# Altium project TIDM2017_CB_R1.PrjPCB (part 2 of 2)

## Sheet Power_Supply.SchDoc
size 431 x 279 mm; Date: Not shown in title block; ApprovedBy: Not shown in title block; CheckedBy: Not shown in title block; Author: Not shown in title block; CompanyName: Not shown in title block; Engineer: Not shown in title block; Organization: Not shown in title block; Address1: Not shown in title block; Address2: Not shown in title block; Address3: Not shown in title block; Address4: Not shown in title block; DocumentNumber: 2; Revision: Use project parameter SCH_Rev; SheetNumber: 2; SheetTotal: 3; PageSetup: Record=PageOptions¦CenterHorizontal=True¦CenterVertical=True¦PrintScale=1.00¦XCorrection=1.00¦YCorrection=1.00¦PrintKind=0¦BorderSize=5000000¦LeftOffset=0¦BottomOffset=0¦Orientation=2¦PaperLength=1000¦PaperWidth=1000¦Scale=100¦PaperSource=15¦PrintQuality=600¦MediaType=1¦DitherType=10¦PaperKind=Letter¦PrintScaleMode=1
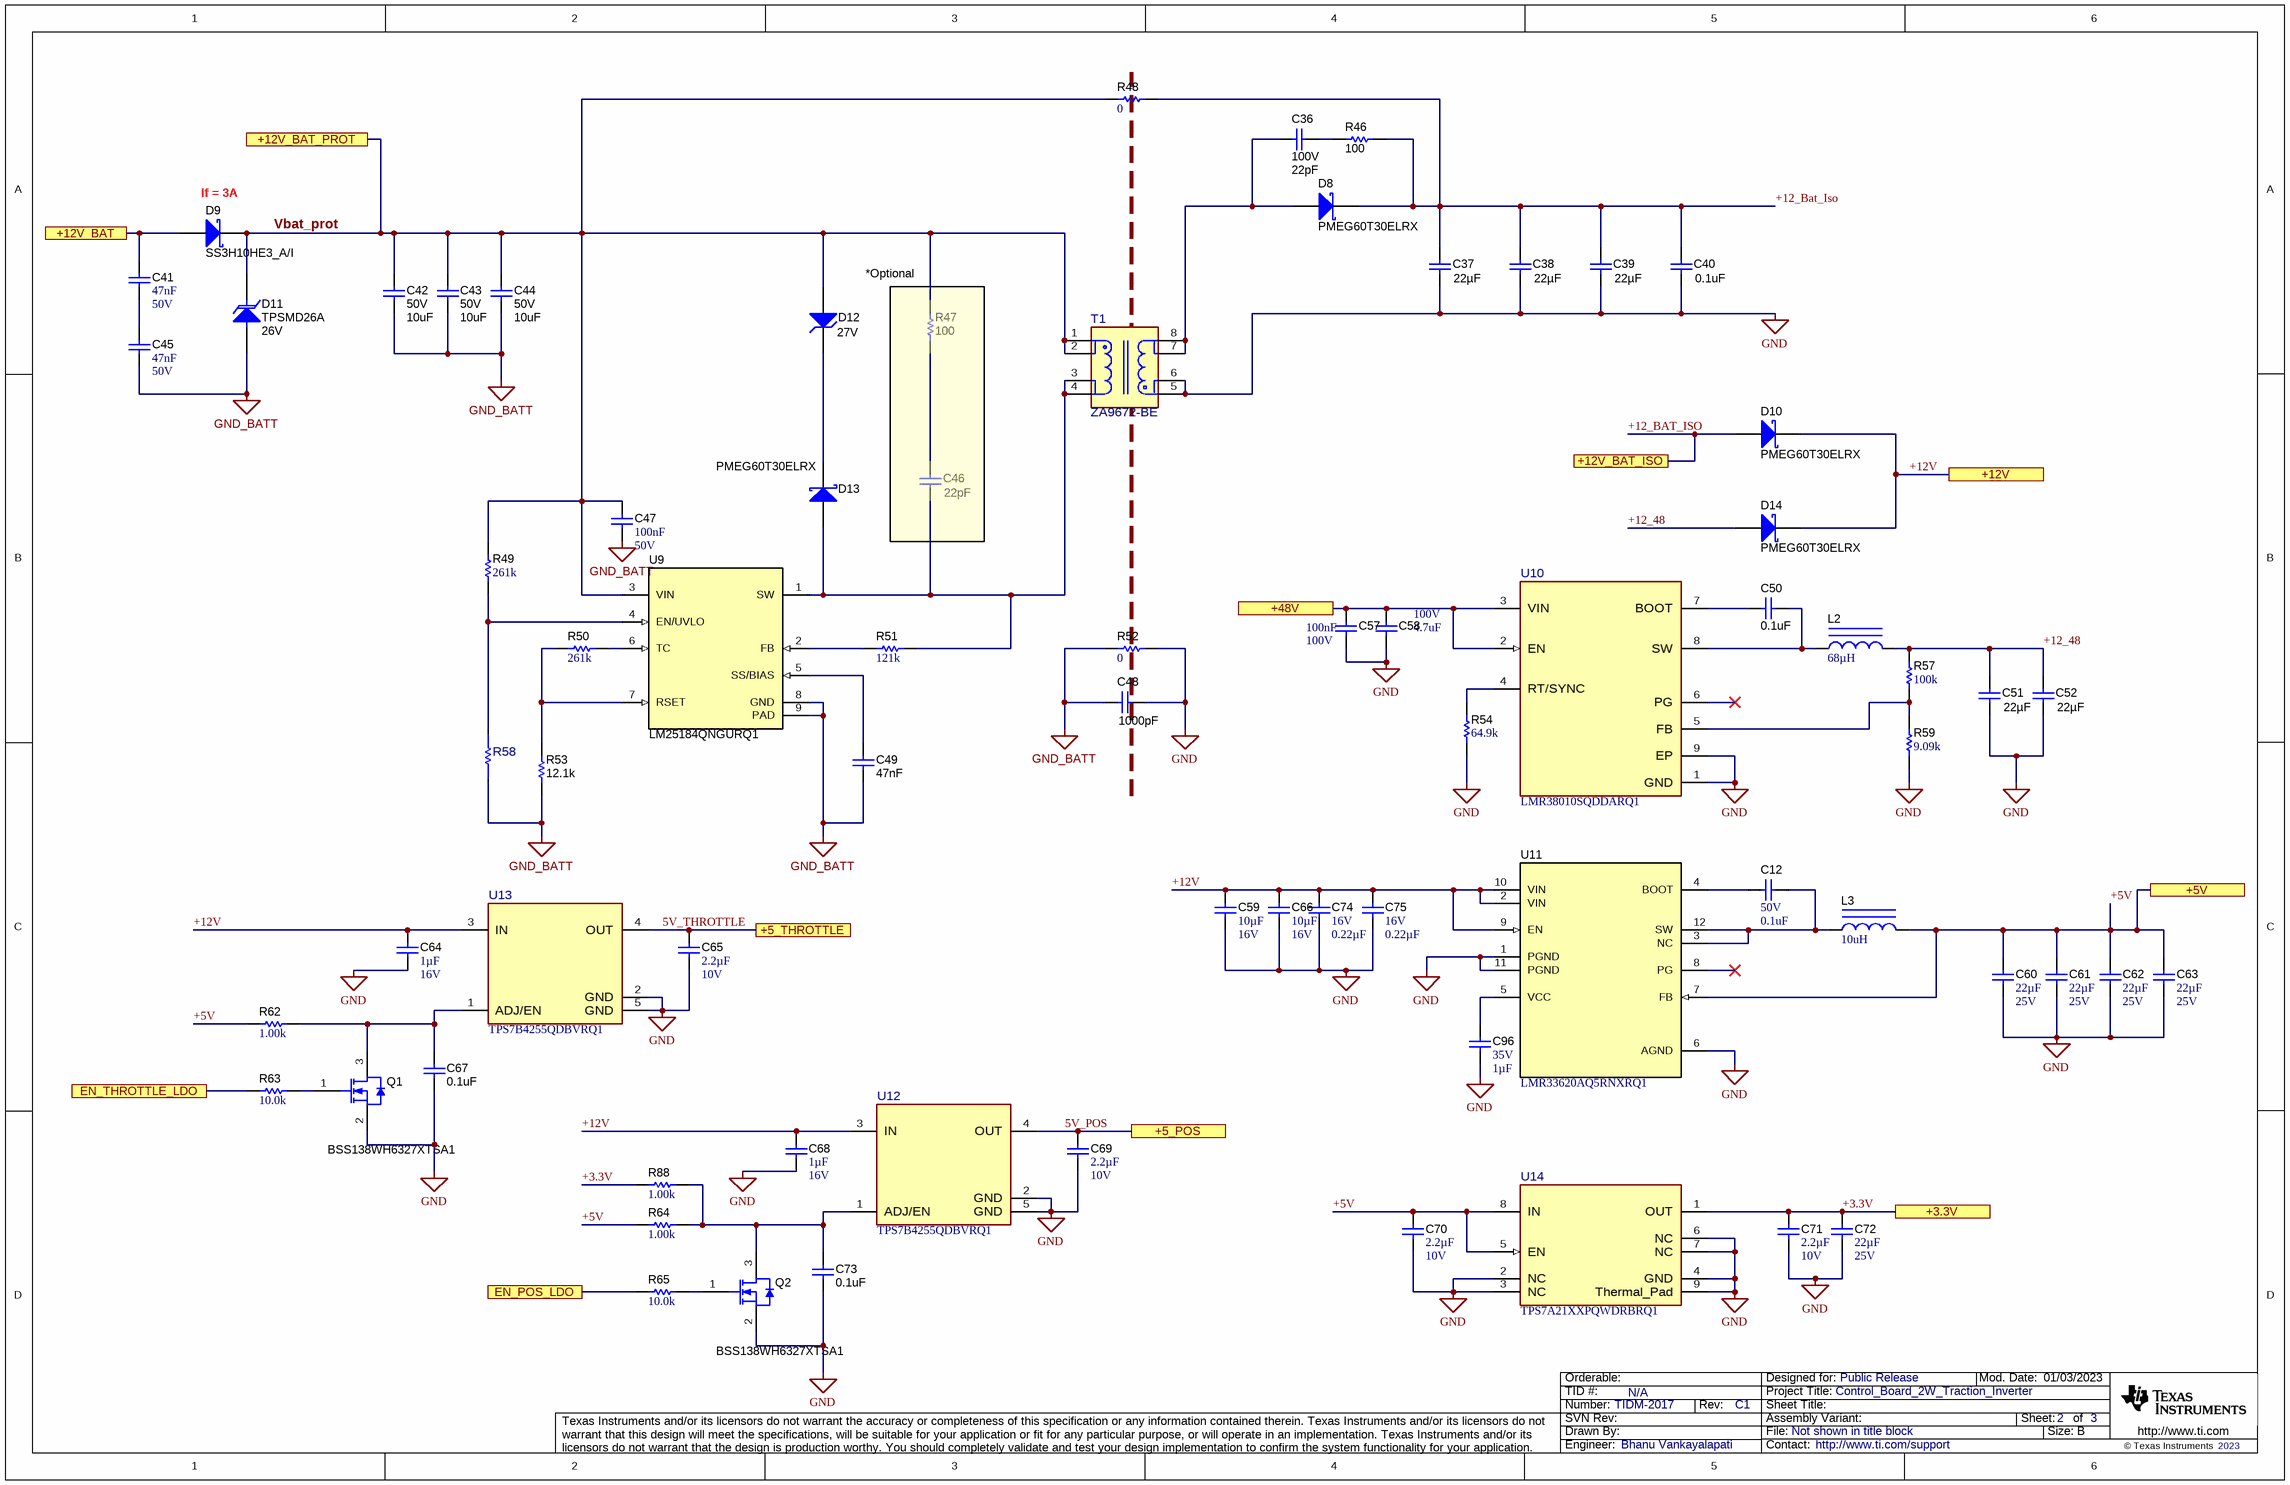
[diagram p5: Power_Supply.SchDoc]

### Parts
C12  VDC_V: 50V  ValueDisplayed: 0.1uF  [0402]  (hidden comment: CGA2B3X7R1H104M050BB)
C36  VDC_V: 100V  ValueDisplayed: 22pF  [0603]  (hidden comment: GRM1885C2A220JA01D)
C37  ValueDisplayed: 22µF  [1210_270]  (hidden comment: TMK325B7226KMHP)
C38  ValueDisplayed: 22µF  [1210_270]  (hidden comment: TMK325B7226KMHP)
C39  ValueDisplayed: 22µF  [1210_270]  (hidden comment: TMK325B7226KMHP)
C40  value 0.1uF  [0603]  (hidden comment: C0603C104K5RACAUTO)
C41  Cap_F: 47nF  VDC_V: 50V  [0603]  (hidden comment: CGA3E2X7R1H473K080AA)
C42  VDC_V: 50V  ValueDisplayed: 10uF  [1210_280]  (hidden comment: CGA6P3X7S1H106K250AB)
C43  VDC_V: 50V  ValueDisplayed: 10uF  [1210_280]  (hidden comment: CGA6P3X7S1H106K250AB)
C44  VDC_V: 50V  ValueDisplayed: 10uF  [1210_280]  (hidden comment: CGA6P3X7S1H106K250AB)
C45  Cap_F: 47nF  VDC_V: 50V  [0603]  (hidden comment: CGA3E2X7R1H473K080AA)
C46  ValueDisplayed: 22pF  [0603_HV]  (hidden comment: GRM1885C2A220JA01D)
C47  Cap_F: 100nF  VDC_V: 50V  [0603]  (hidden comment: C0603C104K5RACTU)
C48  ValueDisplayed: 1000pF  [1206_190M]  (hidden comment: 202R18W102KV4E)
C49  Cap_F: 47nF  [0603]  (hidden comment: GCM188R71E473KA37D)
C50  value 0.1uF  [0603]  (hidden comment: C0603C104K5RACAUTO)
C51  ValueDisplayed: 22µF  [1210_270]  (hidden comment: TMK325B7226KMHP)
C52  ValueDisplayed: 22µF  [1210_270]  (hidden comment: TMK325B7226KMHP)
C57  Cap_F: 100nF  VDC_V: 100V  [0805_HV]  (hidden comment: GCM21BR72A104KA37L)
C58  VDC_V: 100V  ValueDisplayed: 4.7uF  [2220_250]  (hidden comment: CGA9N2X7R2A475M230KA)
C59  ValueDisplayed: 10µF  VDC_V: 16V  [0603]  (hidden comment: GRT188C81C106ME13D)
C60  ValueDisplayed: 22µF  VDC_V: 25V  [0805_HV]  (hidden comment: GRT21BR61E226ME13L)
C61  ValueDisplayed: 22µF  VDC_V: 25V  [0805_HV]  (hidden comment: GRT21BR61E226ME13L)
C62  ValueDisplayed: 22µF  VDC_V: 25V  [0805_HV]  (hidden comment: GRT21BR61E226ME13L)
C63  ValueDisplayed: 22µF  VDC_V: 25V  [0805_HV]  (hidden comment: GRT21BR61E226ME13L)
C64  Cap_F: 1µF  VDC_V: 16V  [0603]  (hidden comment: GCM188R71C105KA64J)
C65  Cap_F: 2.2µF  VDC_V: 10V  [0603]  (hidden comment: GRM188R71A225KE15J)
C66  ValueDisplayed: 10µF  VDC_V: 16V  [0603]  (hidden comment: GRT188C81C106ME13D)
C67  value 0.1uF  [0603]  (hidden comment: C0603C104K5RACAUTO)
C68  Cap_F: 1µF  VDC_V: 16V  [0603]  (hidden comment: GCM188R71C105KA64J)
C69  Cap_F: 2.2µF  VDC_V: 10V  [0603]  (hidden comment: GRM188R71A225KE15J)
C70  Cap_F: 2.2µF  VDC_V: 10V  [0603]  (hidden comment: GRM188R71A225KE15J)
C71  Cap_F: 2.2µF  VDC_V: 10V  [0603]  (hidden comment: GRM188R71A225KE15J)
C72  ValueDisplayed: 22µF  VDC_V: 25V  [0805_HV]  (hidden comment: GRT21BR61E226ME13L)
C73  value 0.1uF  [0603]  (hidden comment: C0603C104K5RACAUTO)
C74  VDC_V: 16V  ValueDisplayed: 0.22µF  [0402]  (hidden comment: GCM155R71C224KE02D)
C75  VDC_V: 16V  ValueDisplayed: 0.22µF  [0402]  (hidden comment: GCM155R71C224KE02D)
C96  VDC_V: 35V  ValueDisplayed: 1µF  [0402]  (hidden comment: GRT155R6YA105KE13D)
D8  PMEG60T30ELRX  [SOD-123W]
D9  SS3H10HE3_A/I  [SMC_265]
D10  PMEG60T30ELRX  [SOD-123W]
D11  TPSMD26A  value 26V  [SMC_265]
D12  value 27V  [SMA]  (hidden comment: 3SMAJ5935B-TP)
D13  PMEG60T30ELRX  [SOD-123W]
D14  PMEG60T30ELRX  [SOD-123W]
L2  ValueDisplayed: 68µH  [PA4342_2]  (hidden comment: PA4342.683NLT)
L3  ValueDisplayed: 10uH  [SRN6045TA]  (hidden comment: SRN6045TA-100M)
Q1  BSS138WH6327XTSA1  [SOT-323]
Q2  BSS138WH6327XTSA1  [SOT-323]
R46  ValueDisplayed: 100  [0603]  (hidden comment: CRCW0603100RFKEAHP)
R47  ValueDisplayed: 100  [0603]  (hidden comment: CRCW0603100RFKEA)
R48  ValueDisplayed: 0  [1206]  (hidden comment: RCA12060000ZSEA)
R49  ValueDisplayed: 261k  [0603]  (hidden comment: CRCW0603261KFKEA)
R50  ValueDisplayed: 261k  [0603]  (hidden comment: CRCW0603261KFKEA)
R51  ValueDisplayed: 121k  [0603]  (hidden comment: CRCW0603121KFKEA)
R52  ValueDisplayed: 0  [1206]  (hidden comment: RCA12060000ZSEA)
R53  ValueDisplayed: 12.1k  [0603]  (hidden comment: CRCW060312K1FKEA)
R54  ValueDisplayed: 64.9k  [0603]  (hidden comment: CRCW060364K9FKEA)
R57  ValueDisplayed: 100k  [0603]  (hidden comment: ERA-3ARW104V)
R58  ERJ-PB3D9762V  [FP-ERJ-PB3D9762V_0603-MFG]  (value not drawn)
R59  ValueDisplayed: 9.09k  [0603]  (hidden comment: CRCW06039K09FKEA)
R62  ValueDisplayed: 1.00k  [0603]  (hidden comment: CRCW06031K00FKEA)
R63  ValueDisplayed: 10.0k  [0603]  (hidden comment: RMCF0603FT10K0)
R64  ValueDisplayed: 1.00k  [0603]  (hidden comment: CRCW06031K00FKEA)
R65  ValueDisplayed: 10.0k  [0603]  (hidden comment: RMCF0603FT10K0)
R88  ValueDisplayed: 1.00k  [0603]  (hidden comment: CRCW06031K00FKEA)
T1  ZA9672-BE  [FP-ZA9672-BE_SMD8-MFG]
U9  LM25184QNGURQ1  [NGU0008C]
U10  LMR38010SQDDARQ1  [DDA0008E-MFG]
U11  LMR33620AQ5RNXRQ1  [RNX0012B]
U12  TPS7B4255QDBVRQ1  [DBV0005A-MFG]
U13  TPS7B4255QDBVRQ1  [DBV0005A-MFG]
U14  TPS7A21XXPQWDRBRQ1  [DRB0008K-MFG]

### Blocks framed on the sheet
*Optional: C46 R47

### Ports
+3.3V, +5_POS, +5_THROTTLE, +5V, +12V, +12V_BAT, +12V_BAT_ISO, +12V_BAT_PROT, +48V, EN_POS_LDO, EN_THROTTLE_LDO

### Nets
+3.3V: C71.1 C72.1 R88.1 U14.1(OUT) ; port +3.3V
+5V: C60.1 C61.1 C62.1 C63.1 C70.1 L3.2 R62.1 R64.1 U11.7(FB) U14.5(EN) U14.8(IN) ; port +5V
GND: C37.2 C38.2 C39.2 C40.2 C48.1 C51.2 C52.2 C57.2 C58.2 C59.2 C60.2 C61.2 C62.2 C63.2 C64.2 C65.2 C66.2 C67.1 C68.2 C69.2 C70.2 C71.2 C72.2 C73.1 C74.2 C75.2 C96.2 Q1.2(S) Q2.2(S) R52.2 R54.1 R59.1 T1.5 T1.6 U10.1(GND) U10.9(EP) U11.1(PGND) U11.6(AGND) U11.11(PGND) U12.2(GND) U12.5(GND) U13.2(GND) U13.5(GND) U14.2(NC) U14.3(NC) U14.4(GND) U14.6(NC) U14.7(NC) U14.9(Thermal_Pad)
GND_BATT: C42.1 C43.1 C44.1 C45.2 C47.2 C48.2 C49.2 D11.2(A) R52.1 R53.1 R58.1 U9.8(GND) U9.9(PAD)
5V_POS: C69.1 U12.4(OUT) ; port +5_POS  [project net +5_POS]
5V_THROTTLE: C65.1 U13.4(OUT) ; port +5_THROTTLE  [project net +5_THROTTLE]
+12_48: C51.1 C52.1 D14.2(A) L2.2 R57.2
+12_Bat_Iso: C37.1 C38.1 C39.1 C40.1 D8.1(K) D10.2(A) R46.2 R48.2 ; port +12V_BAT_ISO
+12V: C59.1 C64.1 C66.1 C68.1 C74.1 C75.1 D10.1(K) D14.1(K) U11.2(VIN) U11.9(EN) U11.10(VIN) U12.3(IN) U13.3(IN) ; port +12V
+12V_BAT: C41.1 D9.2(A) ; port +12V_BAT
+48V: C57.1 C58.1 U10.2(EN) U10.3(VIN) ; port +48V
EN_POS_LDO: R65.1 ; port EN_POS_LDO
EN_THROTTLE_LDO: R63.1 ; port EN_THROTTLE_LDO
Vbat_prot: C42.2 C43.2 C44.2 C47.1 D9.1(K) D11.1(K) D12.2(A) R47.2 R48.1 R49.2 T1.1 T1.2 U9.3(VIN) ; port +12V_BAT_PROT  [project net +12V_BAT_PROT]
NetC12_1: C12.1 L3.1 U11.3(NC) U11.12(SW)
NetC12_2: C12.2 U11.4(BOOT)
NetC36_1: C36.1 R46.1
NetC36_2: C36.2 D8.2(A) T1.7 T1.8
NetC41_2: C41.2 C45.1
NetC46_1: C46.1 R47.1
NetC46_2: C46.2 D13.2(A) R51.2 T1.3 T1.4 U9.1(SW)
NetC49_1: C49.1 U9.5(SS/BIAS)
NetC50_1: C50.1 U10.7(BOOT)
NetC50_2: C50.2 L2.1 U10.8(SW)
NetC67_2: C67.2 Q1.3(D) R62.2 U13.1(ADJ/EN)
NetC73_2: C73.2 Q2.3(D) R64.2 R88.2 U12.1(ADJ/EN)
NetC96_1: C96.1 U11.5(VCC)
NetD12_1: D12.1(K) D13.1(K)
NetQ1_1: Q1.1(G) R63.2
NetQ2_1: Q2.1(G) R65.2
NetR49_1: R49.1 R58.2 U9.4(EN/UVLO)
NetR50_1: R50.1 R53.2 U9.7(RSET)
NetR50_2: R50.2 U9.6(TC)
NetR51_1: R51.1 U9.2(FB)
NetR54_2: R54.2 U10.4(RT/SYNC)
NetR57_1: R57.1 R59.2 U10.5(FB)

Not connected (* = marked no-connect by the designer): U10 6(PG)*; U11 8(PG)*

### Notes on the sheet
- (near D9) If = 3A

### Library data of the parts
C12 = CMP-0006326-2: CAP, CERM, 0.1 uF, 50 V, +/- 20%, X7R, AEC-Q200 Grade 1, 0402; Manufacturer: TDK; TaMin_C: -55°C; Polarized: N; SizeAreaWB_mm2: 3; Value1: Unknown; U/M: EA; Value: 0.1uF; TaMax_C: 125°C; SizeZ_mm: 0.6; SizeX_mm: 1; SizeY_mm: 0.5; AEC Qualified: Y; Cap_F: 100nF; AEC Category: Q200
C36 = CMP-0007255-4: CAP, CERM, 22 pF, 100 V, +/- 5%, C0G/NP0, 0603; Manufacturer: MuRata; TaMin_C: -55°C; Polarized: N; SizeAreaWB_mm2: 4.68; Value1: Unknown; U/M: EA; Value: 22pF; TaMax_C: 125°C; SizeZ_mm: 1; SizeX_mm: 1.6; SizeY_mm: 0.8; SizeArea_mm2: 1.28; AEC Category: Q200
C37-C39 C51 C52 = CMP-0080552-1: CAP, CERM, 22 µF, 25 V,+/- 10%, X7R, AEC-Q200 Grade 1, 1210; Manufacturer: Taiyo Yuden; TaMin_C: -55°C; Polarized: N; SizeAreaWB_mm2: 14.7; U/M: EA; Value: 22uF; TaMax_C: 125°C; SizeZ_mm: 2.7; SizeX_mm: 3.2; SizeY_mm: 2.5; Cap_Case: 1210; Value2: 25V; SizeArea_mm2: 8; CompType: Capacitor; AEC Qualified: Y; AEC Category: Q200; AEC Grade: 1
C40 C50 C67 C73 = CMP-0079602-1: CAP, CERM, 0.1 µF, 50 V,+/- 10%, X7R, AEC-Q200 Grade 1, 0603; Manufacturer: Kemet; TaMin_C: -55°C; Polarized: N; SizeAreaWB_mm2: 4.68; U/M: EA; TaMax_C: 125°C; SizeZ_mm: 1; SizeX_mm: 1.6; SizeY_mm: 0.8; Value2: 50V; SizeArea_mm2: 1.28; AEC Qualified: Y; Cap_F: 100nF; AEC Category: Q200; ValueDisplayed: 0.1µF
C41 C45 = CMP-0007079-4: CAP, CERM, 0.047 uF, 50 V, +/- 10%, X7R, AEC-Q200 Grade 1, 0603; Manufacturer: TDK; TaMin_C: -55°C; ESR_ohm: 49.007m; Polarized: N; SizeAreaWB_mm2: 4.68; Value1: 0.049007 ohm; U/M: EA; TaMax_C: 125°C; SizeZ_mm: 1; SizeX_mm: 1.6; SizeY_mm: 0.8; SizeArea_mm2: 1.28; AEC Qualified: Y; IRMS_A: 767.528mA; AEC Category: Q200
C42-C44 = CMP-0009164-2: CAP, CERM, 10 uF, 50 V, +/- 10%, X7S, AEC-Q200 Grade 1, 1210; Manufacturer: TDK; TaMin_C: -55°C; Polarized: N; SizeAreaWB_mm2: 14.7; Value1: 0.002827 ohm; U/M: EA; Value: 10uF; TaMax_C: 125°C; SizeZ_mm: 2.8; SizeX_mm: 3.2; SizeY_mm: 2.5; SizeArea_mm2: 8; CompType: Capacitor; AEC Qualified: Y; Cap_F: 10µF; AEC Grade: 1; AEC Category: Q200; ESR_ohm: 2.827m; IRMS_A: 4.37286A
C46 = CMP-0007255-4: CAP, CERM, 22 pF, 100 V, +/- 5%, C0G/NP0, 0603; Manufacturer: MuRata; TaMin_C: -55°C; Polarized: N; SizeAreaWB_mm2: 4.68; Value1: Unknown; U/M: EA; Value: 22pF; TaMax_C: 125°C; SizeZ_mm: 1; SizeX_mm: 1.6; SizeY_mm: 0.8; Cap_Case: 0603; Value2: 100V; SizeArea_mm2: 1.28; CompType: Capacitor; AEC Category: Q200
C47 = CMP-0006861-4: CAP, CERM, 0.1 uF, 50 V, +/- 10%, X7R, 0603; Manufacturer: Kemet; TaMin_C: -55°C; Polarized: N; SizeAreaWB_mm2: 4.68; Value1: Unknown; U/M: EA; Value: 0.1uF; TaMax_C: 125°C; SizeZ_mm: 1; SizeX_mm: 1.6; SizeY_mm: 0.8; SizeArea_mm2: 1.28; AEC Category: Q200
C48 = CMP-0008572-2: CAP, CERM, 1000 pF, 2000 V, +/- 10%, X7R, 1206_190; Manufacturer: Johanson Technology; TaMin_C: -55°C; Polarized: N; SizeAreaWB_mm2: 10.92; Value1: Unknown; U/M: EA; Value: 1000pF; TaMax_C: 125°C; SizeZ_mm: 1.9; SizeX_mm: 3.2; SizeY_mm: 1.6; Cap_Case: 1206; Value2: 2000V; SizeArea_mm2: 5.12; CompType: Capacitor; Cap_F: 1nF; VDC_V: 2kV; AEC Category: Q200
C49 = CMP-0007141-3: CAP, CERM, 0.047 uF, 25 V, +/- 10%, X7R, AEC-Q200 Grade 1, 0603; Manufacturer: MuRata; TaMin_C: -55°C; Polarized: N; SizeAreaWB_mm2: 4.68; Value1: Unknown; U/M: EA; TaMax_C: 125°C; SizeZ_mm: 1; SizeX_mm: 1.6; SizeY_mm: 0.8; Value2: 25V; SizeArea_mm2: 1.28; AEC Qualified: Y; AEC Category: Q200
C57 = CMP-0860440-1: CAP, CERM, 0.1 µF, 100 V,+/- 10%, X7R, AEC-Q200 Grade 1, 0805; Manufacturer: MuRata; SizeY_mm: 1.25; ValueDisplayed: 0.1µF; SizeX_mm: 2; Cap_Case: 0805; AEC Grade: 1; Polarized: N; Value: 0.1uF; TaMin_C: -55°C; SizeZ_mm: 1.45; TaMax_C: 125°C; U/M: EA; SizeArea_mm2: 2.5; AEC Qualified: Y; SizeAreaWB_mm2: 6.75; AEC Category: Q200
C58 = CMP-0009414-2: CAP, CERM, 4.7 uF, 100 V, +/- 20%, X7R, AEC-Q200 Grade 1,; Manufacturer: TDK; TaMin_C: -55°C; Polarized: N; SizeAreaWB_mm2: 53.9; Value1: Unknown; U/M: EA; Value: 4.7uF; TaMax_C: 125°C; SizeZ_mm: 2.5; SizeX_mm: 5.7; SizeY_mm: 5; Cap_Case: 2220; SizeArea_mm2: 28.5; AEC Qualified: Y; Cap_F: 4.7µF; AEC Grade: 1; AEC Category: Q200
C59 C66 = CMP-0085644-1: CAP, CERM, 10 µF, 16 V,+/- 20%, X6S, AEC-Q200 Grade 2, 0603; Manufacturer: MuRata; TaMin_C: -55°C; SizeY_mm: 0.8; SizeX_mm: 1.6; SizeZ_mm: 1; SizeArea_mm2: 1.28; Value: 10uF; AEC Grade: 2; Polarized: N; U/M: EA; TaMax_C: 105°C; AEC Qualified: Y; AEC Category: Q200; SizeAreaWB_mm2: 4.68
C60-C63 C72 = CMP-0084680-1: CAP, CERM, 22 µF, 25 V,+/- 20%, X5R, AEC-Q200 Grade 3, 0805; Manufacturer: MuRata; SizeX_mm: 2; SizeAreaWB_mm2: 6.75; Cap_Case: 0805; AEC Grade: 3; SizeY_mm: 1.25; SizeArea_mm2: 2.5; SizeZ_mm: 1.45; U/M: EA; Polarized: N; AEC Category: Q200; Value: 22uF; TaMin_C: -55°C; AEC Qualified: Y; TaMax_C: 85°C
C64 C68 = CMP-0079154-1: CAP, CERM, 1 µF, 16 V,+/- 10%, X7R, AEC-Q200 Grade 1, 0603; Manufacturer: MuRata; SizeAreaWB_mm2: 4.68; SizeArea_mm2: 1.28; AEC Qualified: Y; AEC Category: Q200; Value: 1uF; TaMax_C: 125°C; SizeZ_mm: 1; Polarized: N; TaMin_C: -55°C; SizeY_mm: 0.8; U/M: EA; SizeX_mm: 1.6
C65 C69-C71 = CMP-0084284-1: CAP, CERM, 2.2 µF, 10 V,+/- 10%, X7R, AEC-Q200 Grade 1, 0603; Manufacturer: MuRata; SizeAreaWB_mm2: 4.68; Polarized: N; AEC Qualified: Y; SizeX_mm: 1.6; SizeZ_mm: 1; SizeY_mm: 0.8; U/M: EA; TaMin_C: -55°C; Value: 2.2uF; AEC Category: Q200; TaMax_C: 125°C; SizeArea_mm2: 1.28
C74 C75 = CMP-0078265-1: CAP, CERM, 0.22 µF, 16 V,+/- 10%, X7R, AEC-Q200 Grade 1, 0402; Manufacturer: MuRata; TaMin_C: -55°C; Polarized: N; SizeAreaWB_mm2: 3; U/M: EA; Value: 0.22uF; TaMax_C: 125°C; SizeZ_mm: 0.6; SizeX_mm: 1; SizeY_mm: 0.5; AEC Qualified: Y; Cap_F: 220nF; AEC Category: Q200
C96 = CMP-0750099-1: CAP, CERM, 1 µF, 35 V,+/- 10%, X5R, AEC-Q200 Grade 3, 0402; Manufacturer: MuRata; AEC Grade: 3; AEC Category: Q200; Value: 1uF; SizeArea_mm2: 0.5; SizeZ_mm: 0.6; AEC Qualified: Y; TaMin_C: -55°C; SizeX_mm: 1; U/M: EA; Polarized: N; TaMax_C: 85°C
D8 D10 D13 D14 = CMP-0085903-1: Diode, Schottky, 60 V, 3 A, AEC-Q101, SOD-123W; Manufacturer: Nexperia; Vr_V: 60V; Value1: 3A; TJmax_C: 175°C; Value: 60V; SizeY_mm: 1.7; SizeZ_mm: 1; Vf_V: 620mV; SizeArea_mm2: 5.95; SizeX_mm: 3.5; Value2: 0.62V; SizeAreaWB_mm2: 12.15; AEC Category: Q101; AEC Qualified: Y
D9 = CMP-0077075-2: Diode, Schottky, 100 V, 3 A, AEC-Q101, SMC; Manufacturer: Vishay-Siliconix; Value1: 3A; SizeY_mm: 5.905; Value2: 0.8V; TJmax_C: 175°C; SizeX_mm: 7.94; SizeZ_mm: 2.62; AEC Qualified: Y; Vf_V: 800mV; AEC Category: Q101; Green_REACh: Incomplete; Green_Lifecycle: Not Set; SizeArea_mm2: 46.8857; Vr_V: 100V; SizeAreaWB_mm2: 78.5757; Value: 100V
D11 = CMP-0005729-4: Diode, TVS, Uni, 26 V, 42.1 Vc, AEC-Q101, SMC; Manufacturer: Littelfuse; Vc: 42.1V; Value1: 3000W; Ipp: 71.3A; SizeAreaWB_mm2: 78.5757; AEC Category: Q101; AEC Qualified: Y; SizeArea_mm2: 46.8857; SizeZ_mm: 2.62; Vbr_Max: 31.9V; RJA_CperW: 75; Vbr_Min: 28.9V; Ppk: 3kW; SizeY_mm: 5.905; SizeX_mm: 7.94
D12 = CMP-0005514-4: Diode, Zener, 27 V, 3 W, SMA; Manufacturer: Micro Commercial Components; SizeX_mm: 5.59; SizeY_mm: 2.92; RJA_CperW: 226; SizeZ_mm: 2.87; Value1: 3W; SizeArea_mm2: 16.3228; SizeAreaWB_mm2: 37.3428; AEC Category: Q101
L2 = CMP-0079799-1: Inductor, Shielded, 68 µH, 2 A, 0.24 ohm, AEC-Q200 Grade 1, SMD; Manufacturer: Pulse Engineering; SizeAreaWB_mm2: 166.05; Irms: 2A @ 40C rise; SizeArea_mm2: 118.45; AEC Qualified: Y; AEC Category: Q200; Value: 68uH; SizeZ_mm: 4; Imax_A: 2A; AEC Grade: 1; SizeY_mm: 10.3; Isat: 3A @ 30% inductance drop; DCR_ohm: 0.24; SizeX_mm: 11.5
L3 = CMP-0056765-1: Inductor, Shielded, Ferrite, 10 uH, 3.2 A, 0.0624 ohm, AEC-Q200 Grade 1, SMD; Manufacturer: Bourns; Isat: 4.6A @ 30% inductance drop; Irms: 3.2A @ 40C rise; Green_Lifecycle: Active; SizeAreaWB_mm2: 64; DCR_ohm: 62.4m; Green_REACh: Passed; Value: 10uH; Imax_A: 3.2A; SizeZ_mm: 4.5; SizeX_mm: 6; SizeArea_mm2: 36; Ind_H: 10µH; AEC Qualified: Y; AEC Grade: 1; AEC Category: Q200
Q1 Q2 = CMP-0000791-1: MOSFET, N-CH, 60 V, 0.28 A, AEC-Q101, SOT-323; Alternate Manufacturer: None; Manufacturer: Infineon Technologies; SizeZ_mm: 1.1; ChType: N; Value2: 1 nC; VdsMax_V: 60V; SizeX_mm: 2.2; Vgs_V: 20V; QgTyp_nC: 1; AEC Qualified: Y; Value: 60V; Rdson45_ohm: 4; SizeArea_mm2: 4.84; AEC Category: Q101; IdsMax_A: 280mA; SizeAreaWB_mm2: 10.24; U/M: EA
R46 = CMP-0084243-1: RES, 100, 1%, 0.25 W, AEC-Q200 Grade 0, 0603; Manufacturer: Vishay-Dale; Power_W: 250mW; TempCo: 100 ppm/C; SizeAreaWB_mm2: 4.68; Value_Code: 100R; Value: 100; EIA_Code: E96; SizeX_mm: 1.6; SizeY_mm: 0.8; SizeZ_mm: 1; Value2: 0.25W; SizeArea_mm2: 1.28; AEC Qualified: Y; AEC Grade: 0; AEC Category: Q200
R47 = CMP-0021991-4: RES, 100, 1%, 0.1 W, AEC-Q200 Grade 0, 0603; Manufacturer: Vishay-Dale; Power_W: 100mW; TempCo: 100 ppm/C; Value_Code: 100R; Value: 100; EIA_Code: E96; SizeX_mm: 1.6; SizeY_mm: 0.8; SizeZ_mm: 1; Value2: 0.1W; SizeArea_mm2: 1.28; AEC Qualified: Y; VDC_V: 75V; AEC Category: Q200; AEC Grade: 0
R48 R52 = CMP-0018760-2: RES, 0, 5%, 0.25 W, AEC-Q200 Grade 0, 1206; Manufacturer: Vishay-Dale; Power_W: 250mW; TempCo: ppm/C; Value_Code: 0000; U/M: EA; Value: 0; EIA_Code: E24; SizeX_mm: 3.2; SizeY_mm: 1.6; SizeZ_mm: 1.35; Value2: 0.25W; SizeArea_mm2: 5.12; AEC Qualified: Y; AEC Category: Q200
R49 R50 = CMP-0022244-4: RES, 261 k, 1%, 0.1 W, AEC-Q200 Grade 0, 0603; Manufacturer: Vishay-Dale; Power_W: 100mW; TempCo: 100 ppm/C; Value: 261k; EIA_Code: E96; SizeX_mm: 1.6; SizeY_mm: 0.8; SizeZ_mm: 1; Value2: 0.1W; SizeArea_mm2: 1.28; AEC Qualified: Y; VDC_V: 75V; AEC Category: Q200; AEC Grade: 0
R51 = CMP-0022024-4: RES, 121 k, 1%, 0.1 W, AEC-Q200 Grade 0, 0603; Manufacturer: Vishay-Dale; Power_W: 100mW; TempCo: 100 ppm/C; Value: 121k; EIA_Code: E96; SizeX_mm: 1.6; SizeY_mm: 0.8; SizeZ_mm: 1; Value2: 0.1W; SizeArea_mm2: 1.28; AEC Qualified: Y; VDC_V: 75V; AEC Category: Q200; AEC Grade: 0
R53 = CMP-0022030-4: RES, 12.1 k, 1%, 0.1 W, AEC-Q200 Grade 0, 0603; Manufacturer: Vishay-Dale; Power_W: 100mW; TempCo: 100 ppm/C; Value_Code: 12k1; Value: 12.1k; EIA_Code: E96; SizeX_mm: 1.6; SizeY_mm: 0.8; SizeZ_mm: 1; Value2: 0.1W; SizeArea_mm2: 1.28; AEC Qualified: Y; VDC_V: 75V; AEC Category: Q200; AEC Grade: 0
R54 = CMP-0022544-4: RES, 64.9 k, 1%, 0.1 W, AEC-Q200 Grade 0, 0603; Manufacturer: Vishay-Dale; Power_W: 100mW; TempCo: 100 ppm/C; Value_Code: 64k9; Value: 64.9k; EIA_Code: E96; SizeX_mm: 1.6; SizeY_mm: 0.8; SizeZ_mm: 1; Value2: 0.1W; SizeArea_mm2: 1.28; AEC Qualified: Y; VDC_V: 75V; AEC Category: Q200; AEC Grade: 0
R57 = CMP-0023385-3: RES, 100 k, 0.05%, 0.1 W, AEC-Q200 Grade 0, 0603; Manufacturer: Panasonic; Power_W: 100mW; TempCo: 10 ppm/C; U/M: EA; Value: 100k; SizeX_mm: 1.6; SizeY_mm: 0.8; SizeZ_mm: 1; Value2: 0.1W; SizeArea_mm2: 1.28; AEC Qualified: Y; VDC_V: 75V; AEC Grade: 0; AEC Category: Q200
R58 = CMP-0031885-1: 97.6 kOhms ±0.5% 0.2W, 1/5W Chip Resistor 0603 (1608 Metric) Automotive AEC-Q200, Pulse Withstanding Thick Film; Manufacturer: Panasonic; AEC Grade: Grade 0; AEC Qualified: Yes; Power_W: 200mW; Res_ohm: 97.6k; SizeZ_mm: 0.55mm; TempCo: 50ppm/°C; VDC_V: 150V; Value: 97.6k
R59 = CMP-0022665-4: RES, 9.09 k, 1%, 0.1 W, AEC-Q200 Grade 0, 0603; Manufacturer: Vishay-Dale; Power_W: 100mW; TempCo: 100 ppm/C; Value_Code: 9k09; Value: 9.09k; EIA_Code: E96; SizeX_mm: 1.6; SizeY_mm: 0.8; SizeZ_mm: 1; Value2: 0.1W; SizeArea_mm2: 1.28; AEC Qualified: Y; VDC_V: 75V; AEC Category: Q200; AEC Grade: 0
R62 R64 R88 = CMP-0022109-5: RES, 1.00 k, 1%, 0.1 W, AEC-Q200 Grade 0, 0603; Manufacturer: Vishay-Dale; Power_W: 100mW; TempCo: 100 ppm/C; Value_Code: 1k00; Value: 1.00k; EIA_Code: E96; Res_ohm: 1k; SizeX_mm: 1.6; SizeY_mm: 0.8; SizeZ_mm: 1; Value2: 0.1W; SizeArea_mm2: 1.28; AEC Qualified: Y; VDC_V: 75V; AEC Category: Q200; AEC Grade: 0
R63 R65 = CMP-0023341-3: RES, 10.0 k, 1%, 0.1 W, AEC-Q200 Grade 0, 0603; Manufacturer: Stackpole Electronics Inc; Power_W: 100mW; TempCo: 100 ppm/C; Value_Code: 10k0; U/M: EA; Value: 10.0k; EIA_Code: E96; Res_ohm: 10k; SizeX_mm: 1.6; SizeY_mm: 0.8; SizeZ_mm: 1; Value2: 0.1W; SizeArea_mm2: 1.28; AEC Qualified: Y; VDC_V: 75V; AEC Grade: 0; AEC Category: Q200
T1 = CMP-0088070-1: FLYBACK TRANSFORMER; Manufacturer: Coilcraft; DCR_ohm: 35m; Ind_H: 6.3µH; Ns1toNp: 1:1; SizeZ_mm: 10mm; AEC Qualified: No
U9 = CMP-0860959-2: 42-VIN PSR Flyback DC/DC Converter with 65-V, 4-A Integrated MOSFET, NGU0008C (WSON-8); Manufacturer: Texas Instruments; SizeArea_mm2: 16; SizeY_mm: 4; SizeAreaWB_mm2: 25; CompType: IC; AEC Category: Q200; SizeZ_mm: 0.8; AEC Qualified: Y
U10 = CMP-0097344-1: 4.2-V to 80-V, 1-A Synchronous Buck Converter with 40-µA IQ; Manufacturer: Texas Instruments; SizeZ_mm: 1.7mm; Output Voltage: 1-75V; Max Duty Cycle: 97%; Number Of Outputs: 1; TJmax_C: +150°C; Output Type: AdjustableProgrammable; Switching Frequency: 200-2200kHz; AEC Qualified: Yes; Nominal Supply Current: 40uA; Standoff Height: 0mm; Min Supply Voltage: 4.2V; Max Supply Voltage: 80V
U11 = CMP-0860362-1: 3.8-V to 36-V, 2-A Synchronous step-down voltage converter, RNX0012B (VQFN-HR-12); Alternate PartNumber: LMR33620AQ5RNXTQ1; Alternate Manufacturer: Texas Instruments; Rating: Automotive; SizeArea_mm2: 6; SizeZ_mm: 0.9; SizeAreaWB_mm2: 12; AEC Qualified: Y; AEC Category: Q200; CompType: IC; SizeY_mm: 3; SizeX_mm: 2
U12 U13 = CMP-0096536-1: Automotive, 70-mA, 40-V, Voltage-Tracking LDO With 5-mV Tracking Tolerance, SOT23-5; Manufacturer: Texas Instruments; SizeZ_mm: 1.45mm; Standoff Height: 0mm; Max Supply Voltage: 40V; TaMax_C: +125°C; Dropout Voltage: 500mV; AEC Qualified: Yes; Min Supply Voltage: 3V; Output Voltage: 2-40V; AEC Grade: Grade 1; Nominal Supply Current: 600-800uA; Number Of Outputs: 1; TaMin_C: -40°C; TJmax_C: +150°C; Output Type: AdjustableProgrammable
U14 = CMP-0096433-1: Automotive, 500-mA, Low-Noise, Low-IQ, High-PSRR LDO; Manufacturer: Texas Instruments; Output Type: AdjustableProgrammable; Min Supply Voltage: 2V; TJmax_C: +150°C; Output Voltage: 0.8-5.5V; Accuracy Percentage: 1.5%; Dropout Voltage: 750mV; AEC Qualified: Yes; Nominal Supply Current: 6.5uA; Standoff Height: 0mm; SizeZ_mm: 1mm; Number Of Outputs: 1; AEC Grade: Grade 0; Max Supply Voltage: 6V

## Sheet Position_Sensing.SchDoc
size 431 x 279 mm; Date: Not shown in title block; ApprovedBy: Not shown in title block; CheckedBy: Not shown in title block; Author: Not shown in title block; CompanyName: Not shown in title block; Engineer: Not shown in title block; Organization: Not shown in title block; Address1: Not shown in title block; Address2: Not shown in title block; Address3: Not shown in title block; Address4: Not shown in title block; DocumentNumber: 2; Revision: Use project parameter SCH_Rev; SheetNumber: 2; SheetTotal: 3; PageSetup: Record=PageOptions¦CenterHorizontal=True¦CenterVertical=True¦PrintScale=1.00¦XCorrection=1.00¦YCorrection=1.00¦PrintKind=0¦BorderSize=5000000¦LeftOffset=0¦BottomOffset=0¦Orientation=2¦PaperLength=1000¦PaperWidth=1000¦Scale=100¦PaperSource=15¦PrintQuality=600¦MediaType=1¦DitherType=10¦PaperKind=Letter¦PrintScaleMode=1
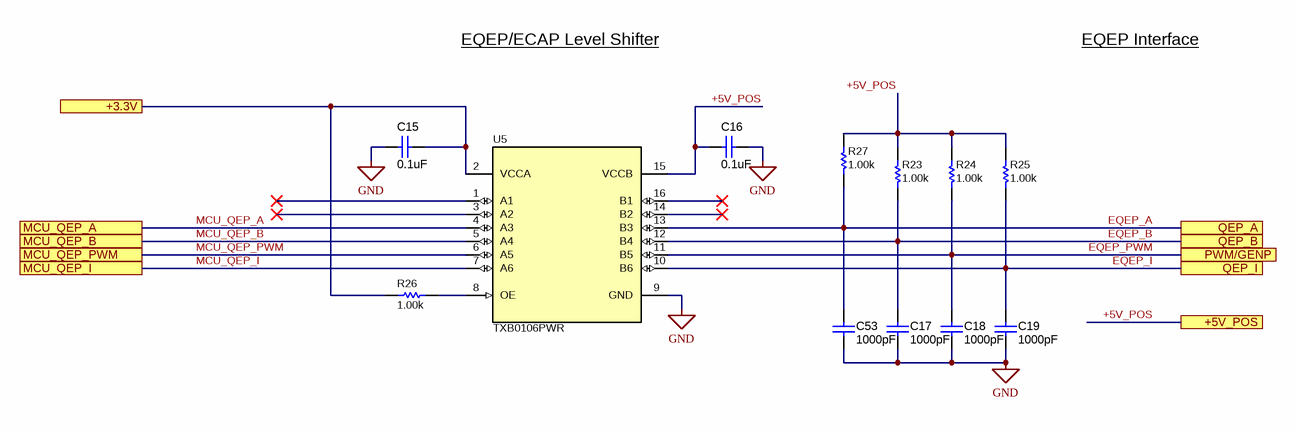
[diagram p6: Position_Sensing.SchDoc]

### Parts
C15  ValueDisplayed: 0.1uF  [0603]  (hidden comment: CGA3E2X7R1H104K080AA)
C16  ValueDisplayed: 0.1uF  [0603]  (hidden comment: CGA3E2X7R1H104K080AA)
C17  ValueDisplayed: 1000pF  [0603]  (hidden comment: GRM1885C1H102JA01D)
C18  ValueDisplayed: 1000pF  [0603]  (hidden comment: GRM1885C1H102JA01D)
C19  ValueDisplayed: 1000pF  [0603]  (hidden comment: GRM1885C1H102JA01D)
C53  ValueDisplayed: 1000pF  [0603]  (hidden comment: GRM1885C1H102JA01D)
R23  ValueDisplayed: 1.00k  [0603]  (hidden comment: CRCW06031K00FKEA)
R24  ValueDisplayed: 1.00k  [0603]  (hidden comment: CRCW06031K00FKEA)
R25  ValueDisplayed: 1.00k  [0603]  (hidden comment: CRCW06031K00FKEA)
R26  ValueDisplayed: 1.00k  [0603]  (hidden comment: CRCW06031K00FKEA)
R27  ValueDisplayed: 1.00k  [0603]  (hidden comment: CRCW06031K00FKEA)
U5  TXB0106PWR  [PW0016A_N]

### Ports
+3.3V, +5V_POS, MCU_QEP_A, MCU_QEP_B, MCU_QEP_I, MCU_QEP_PWM, PWM/GENP, QEP_A, QEP_B, QEP_I

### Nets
+3.3V: C15.1 R26.1 U5.2(VCCA) ; port +3.3V
GND: C15.2 C16.1 C17.2 C18.2 C19.2 C53.2 U5.9(GND)
+5V_POS: C16.2 R23.2 R24.2 R25.2 R27.2 U5.15(VCCB) ; port +5V_POS  [project net +5_POS]
EQEP_A: C53.1 R27.1 U5.13(B3) ; port QEP_A
EQEP_B: C17.1 R23.1 U5.12(B4) ; port QEP_B
EQEP_I: C19.1 R25.1 U5.10(B6) ; port QEP_I
EQEP_PWM: C18.1 R24.1 U5.11(B5) ; port PWM/GENP
MCU_QEP_A: U5.4(A3) ; port MCU_QEP_A
MCU_QEP_B: U5.5(A4) ; port MCU_QEP_B
MCU_QEP_I: U5.7(A6) ; port MCU_QEP_I
MCU_QEP_PWM: U5.6(A5) ; port MCU_QEP_PWM
NetR26_2: R26.2 U5.8(OE)

Not connected (* = marked no-connect by the designer): U5 1(A1)* 3(A2)* 14(B2)* 16(B1)*

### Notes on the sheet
- EQEP/ECAP Level Shifter
- EQEP Interface

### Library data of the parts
C15 C16 = CMP-0007078-4: CAP, CERM, 0.1 uF, 50 V, +/- 10%, X7R, AEC-Q200 Grade 1, 0603; Manufacturer: TDK; Polarized: N; Value: 0.1uF; U/M: EA; Cap_F: 100nF; ESR_ohm: 29.6m; Value1: 0.0296 ohm; VDC_V: 50V; IRMS_A: 971.99mA; TaMin_C: -55°C; TaMax_C: 125°C; SizeArea_mm2: 1.28; SizeAreaWB_mm2: 4.68; SizeX_mm: 1.6; SizeY_mm: 0.8; SizeZ_mm: 1; AEC Category: Q200; AEC Qualified: Y
C17-C19 C53 = CMP-0007173-4: CAP, CERM, 1000 pF, 50 V, +/- 5%, C0G/NP0, 0603; Manufacturer: MuRata; Polarized: N; Value: 1000pF; U/M: EA; Cap_F: 1nF; Value1: Unknown; VDC_V: 50V; TaMin_C: -55°C; TaMax_C: 125°C; SizeArea_mm2: 1.28; SizeAreaWB_mm2: 4.68; SizeX_mm: 1.6; SizeY_mm: 0.8; SizeZ_mm: 1; AEC Category: Q200
R23-R27 = CMP-0022109-5: RES, 1.00 k, 1%, 0.1 W, AEC-Q200 Grade 0, 0603; Manufacturer: Vishay-Dale; Value: 1.00k; Res_ohm: 1k; Value_Code: 1k00; Power_W: 100mW; Value2: 0.1W; VDC_V: 75V; TempCo: 100 ppm/C; SizeArea_mm2: 1.28; SizeX_mm: 1.6; SizeY_mm: 0.8; SizeZ_mm: 1; EIA_Code: E96; AEC Category: Q200; AEC Qualified: Y; AEC Grade: 0
U5 = CMP-0067443-1: 6-Bit Bidirectional Voltage-Level Translator with Auto Direction Sensing and +/-15-kV ESD Protect, PW0016A (TSSOP-16); Manufacturer: Texas Instruments; SizeArea_mm2: 32.0; SizeAreaWB_mm2: 58.8; SizeX_mm: 6.4; SizeY_mm: 5.0; SizeZ_mm: 1.2; CompType: IC; U/M: EA; Green_Lifecycle: Active; Green_REACh: Passed

## Sheet TIDM2017_CB_R1_Hardware.SchDoc
size 431 x 279 mm; Date: Not shown in title block; ApprovedBy: Not shown in title block; CheckedBy: Not shown in title block; Author: Not shown in title block; CompanyName: Not shown in title block; DrawnBy: Bhanu Vankayalapati; Engineer: Not shown in title block; Organization: Not shown in title block; Address1: Not shown in title block; Address2: Not shown in title block; Address3: Not shown in title block; Address4: Not shown in title block; DocumentNumber: 3; Revision: Use project parameter SCH_Rev; SheetNumber: 2; SheetTotal: 2; PageSetup: Record=PageOptions¦CenterHorizontal=True¦CenterVertical=True¦PrintScale=1.00¦XCorrection=1.00¦YCorrection=1.00¦PrintKind=0¦BorderSize=5000000¦LeftOffset=0¦BottomOffset=0¦Orientation=2¦PaperLength=1000¦PaperWidth=1000¦Scale=100¦PaperSource=15¦PrintQuality=600¦MediaType=1¦DitherType=10¦PaperKind=Letter¦PrintScaleMode=1
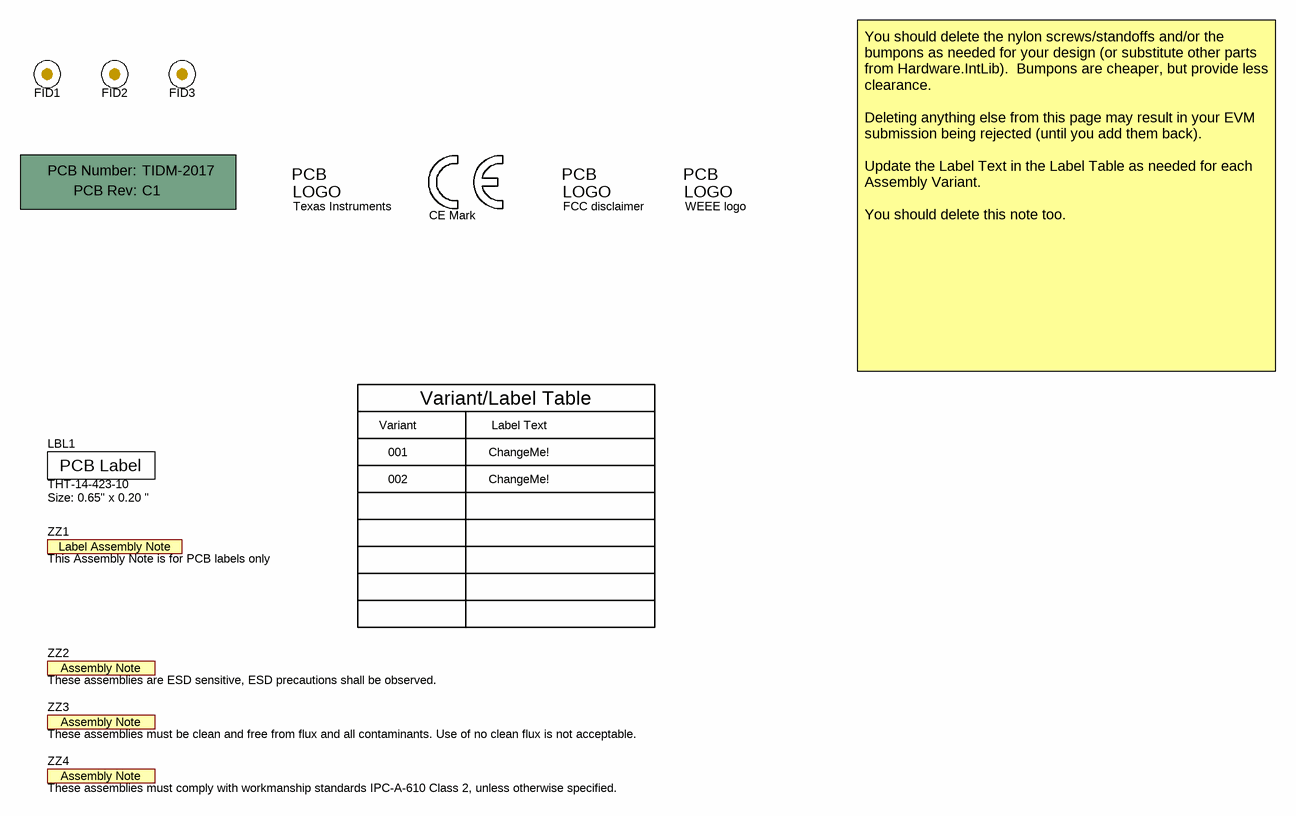
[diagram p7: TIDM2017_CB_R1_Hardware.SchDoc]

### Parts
!PCB  Printed Circuit Board  (value not drawn)  (mechanical)
FID1  Fiducial  [Fiducial10-20]  (value not drawn)
FID2  Fiducial  [Fiducial10-20]  (value not drawn)
FID3  Fiducial  [Fiducial10-20]  (value not drawn)
LBL1  THT-14-423-10  Note: Size: 0.65" x 0.20 "  [Label_650x200]
Logo1  Texas Instruments  [TI_Stacked_Overlay_Small]  (no BOM)
Logo2  CE Mark  [CE_Mark_5mm]  (no BOM)
Logo3  FCC disclaimer  [FCC_disclaimer]  (no BOM)
Logo4  WEEE logo  [WEEE_Minimum]  (no BOM)
ZZ1  This Assembly Note is for PCB labels only  [AssemblyNoteLabel]  (no BOM)
ZZ2  These assemblies are ESD sensitive, ESD precautions shall be observed.  [AssemblyNote]  (no BOM)
ZZ3  These assemblies must be clean and free from flux and all contaminants. Use of no clean flux is not acceptable.  [AssemblyNote]  (no BOM)
ZZ4  These assemblies must comply with workmanship standards IPC-A-610 Class 2, unless otherwise specified.  [AssemblyNote]  (no BOM)

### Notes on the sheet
- Variant
- Variant/Label Table
- Label Text
- You should delete the nylon screws/standoffs and/or the bumpons as needed for your design (or substitute other parts from Hardware.IntLib).  Bumpons are cheaper, but provide less clearance.
  Deleting anything else from this page may result in your EVM submission being rejected (until you add them back).
  Update the Label Text in the Label Table as needed for each Assembly Variant.
  You should delete this note too.
- 001
- 002
- ChangeMe!

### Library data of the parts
!PCB = CMP-0003618-2: Manufacturer: Any
FID1-FID3 = CMP-0077181-1: Fiducial mark.  There is nothing to buy or mount.
LBL1 = CMP-0003625-1: Thermal Transfer Printable Labels, 0.650" W x 0.200" H - 10,000 per roll; Manufacturer: Brady; CompType: Label
Logo1 = CMP-0074838-1: Texas Instrument Corporate Signature; SymbolCreator: a0412235; Lib Reference: TI_Logo; Library Reference: Logo
Logo2 = CMP-0074844-1: SymbolCreator: a0412235
Logo3 = CMP-0074847-1: FCC_disclaimer; Library Reference: Logo
Logo4 = CMP-0074769-1
ZZ1 = CMP-0003616-3
ZZ2 = CMP-0077236-1
ZZ3 = CMP-0077237-1
ZZ4 = CMP-0077238-1

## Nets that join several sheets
+3.3V: C2000_Control_Card (D1.2 D2.2 D3.2 R11.2), CAN_Comm (5 pins), Input_Signal_Conditioning (8 pins), Gate_Drive (C76.1 R21.1 R22.1 U2.11), Power_Supply (C71.1 C72.1 R88.1 U14.1), Position_Sensing (C15.1 R26.1 U5.2)
+5V: C2000_Control_Card (8 pins), Input_Signal_Conditioning (J11.1 J12.1 J13.1), Power_Supply (11 pins)
GND: TIDM2017_CB_R1 (11 pins), C2000_Control_Card (35 pins), CAN_Comm (5 pins), Input_Signal_Conditioning (44 pins), Gate_Drive (14 pins), Power_Supply (49 pins), Position_Sensing (7 pins)
GND_BATT: TIDM2017_CB_R1 (J16.3 J16.4), CAN_Comm (21 pins), Power_Supply (13 pins)
12V_BAT_SENSE: C2000_Control_Card (J3.26), Input_Signal_Conditioning (C95.2 R10.2 R87.2)
+5_POS: TIDM2017_CB_R1 (J16.7), C2000_Control_Card (J14.9), Input_Signal_Conditioning (R70.1), Power_Supply (C69.1 U12.4), Position_Sensing (6 pins)
+5_THROTTLE: TIDM2017_CB_R1 (J17.3 J17.4), Input_Signal_Conditioning (R72.1), Power_Supply (C65.1 U13.4)
+12_Bat_Iso: Input_Signal_Conditioning (R10.1), Power_Supply (8 pins)
+12V: Gate_Drive (7 pins), Power_Supply (13 pins)
+12V_BAT: TIDM2017_CB_R1 (J16.5 J16.6), Power_Supply (C41.1 D9.2)
+12V_BAT_PROT: CAN_Comm (C33.1 U8.1), Power_Supply (13 pins)
+48V: Gate_Drive (5 pins), Power_Supply (C57.1 C58.1 U10.2 U10.3)
AMR_COS_N: C2000_Control_Card (J3.33), Input_Signal_Conditioning (C94.2 R85.2 R86.2)
AMR_COS_P: C2000_Control_Card (J3.31), Input_Signal_Conditioning (C89.2 R79.2 R82.2)
AMR_COSN_IN: TIDM2017_CB_R1 (J17.8), Input_Signal_Conditioning (R85.1)
AMR_COSP_IN: TIDM2017_CB_R1 (J17.7), Input_Signal_Conditioning (R79.1)
AMR_SIN_N: C2000_Control_Card (J3.27), Input_Signal_Conditioning (C86.2 R77.2 R78.2)
AMR_SIN_P: C2000_Control_Card (J3.25), Input_Signal_Conditioning (C85.2 R74.2 R76.2)
AMR_SINN_IN: TIDM2017_CB_R1 (J17.6), Input_Signal_Conditioning (R77.1)
AMR_SINP_IN: TIDM2017_CB_R1 (J17.5), Input_Signal_Conditioning (R74.1)
CAN_EN_MCU: C2000_Control_Card (J3.92), CAN_Comm (R44.1 U7.3)
CAN_H: TIDM2017_CB_R1 (J16.2), CAN_Comm (6 pins)
CAN_L: TIDM2017_CB_R1 (J16.1), CAN_Comm (6 pins)
DRV_ASCSEL: C2000_Control_Card (J3.61), Gate_Drive (U2.8)
DRV_DRVOFF: C2000_Control_Card (J3.59 R11.1), Gate_Drive (U2.10)
DRV_nASCIN: C2000_Control_Card (J3.63), Gate_Drive (U2.9)
DRV_nFLT1: C2000_Control_Card (J3.57), Gate_Drive (R21.2 U2.13)
DRV_nSLEEP: C2000_Control_Card (J3.58), Gate_Drive (U2.14)
DRV_PHCA: C2000_Control_Card (J3.103), Gate_Drive (R14.2 U2.59)
DRV_PHCB: C2000_Control_Card (J3.101), Gate_Drive (R19.2 U2.60)
DRV_PHCC: C2000_Control_Card (J3.99), Gate_Drive (R20.2 U2.61)
DRV_PWM_AH: C2000_Control_Card (J3.49), Gate_Drive (U2.2)
DRV_PWM_AL: C2000_Control_Card (J3.51), Gate_Drive (U2.3)
DRV_PWM_BH: C2000_Control_Card (J3.53), Gate_Drive (U2.4)
DRV_PWM_BL: C2000_Control_Card (J3.55), Gate_Drive (U2.5)
DRV_PWM_CH: C2000_Control_Card (J3.50), Gate_Drive (U2.6)
DRV_PWM_CL: C2000_Control_Card (J3.52), Gate_Drive (U2.7)
DRV_SPI_CLK: C2000_Control_Card (J3.79), Gate_Drive (U2.63)
DRV_SPI_CS: C2000_Control_Card (J3.81), Gate_Drive (U2.64)
DRV_SPI_SDI: C2000_Control_Card (J3.75), Gate_Drive (U2.62)
DRV_SPI_SDO: C2000_Control_Card (J3.77), Gate_Drive (U2.1)
EN_POS_LDO: C2000_Control_Card (J3.110), Power_Supply (R65.1)
EN_THROTTLE_LDO: C2000_Control_Card (J3.60), Power_Supply (R63.1)
EQEP_A: TIDM2017_CB_R1 (J16.15), Position_Sensing (C53.1 R27.1 U5.13)
EQEP_B: TIDM2017_CB_R1 (J16.13), Position_Sensing (C17.1 R23.1 U5.12)
EQEP_I: TIDM2017_CB_R1 (J16.9), Position_Sensing (C19.1 R25.1 U5.10)
EQEP_PWM: TIDM2017_CB_R1 (J16.11), Position_Sensing (C18.1 R24.1 U5.11)
ILEM_A_MCU: C2000_Control_Card (J3.15), Input_Signal_Conditioning (C21.1 R30.2)
ILEM_B_MCU: C2000_Control_Card (J3.18), Input_Signal_Conditioning (C22.1 R15.2)
ILEM_C_MCU: C2000_Control_Card (J3.34), Input_Signal_Conditioning (C55.1 R31.2)
INV_TEMP: TIDM2017_CB_R1 (J17.9), Input_Signal_Conditioning (R83.1)
MCAN_RX: C2000_Control_Card (J3.80), CAN_Comm (R42.1 U7.5)
MCAN_TX: C2000_Control_Card (J3.82), CAN_Comm (R43.1 U7.4)
MCU_INV_TEMP: C2000_Control_Card (J3.24), Input_Signal_Conditioning (C90.1 R81.2)
MCU_MOTOR_TEMP: C2000_Control_Card (J3.37), Input_Signal_Conditioning (C81.1 R67.2)
MCU_QEP_A: C2000_Control_Card (J3.68), Position_Sensing (U5.4)
MCU_QEP_B: C2000_Control_Card (J3.70), Position_Sensing (U5.5)
MCU_QEP_I: C2000_Control_Card (J3.74), Position_Sensing (U5.7)
MCU_QEP_PWM: C2000_Control_Card (J3.72), Position_Sensing (U5.6)
MCU_THROTTLE_1: C2000_Control_Card (J3.28), Input_Signal_Conditioning (C77.1 R6.2)
MCU_THROTTLE_2: C2000_Control_Card (J3.40), Input_Signal_Conditioning (C79.1 R9.2)
MOTOR_TEMP: TIDM2017_CB_R1 (J17.11), Input_Signal_Conditioning (R68.1)
POS_LDO_SENSE: C2000_Control_Card (J3.12), Input_Signal_Conditioning (C83.2 R70.2 R71.2)
THROTTLE_1: TIDM2017_CB_R1 (J17.15), Input_Signal_Conditioning (R7.1)
THROTTLE_2: TIDM2017_CB_R1 (J17.13), Input_Signal_Conditioning (R12.1)
THROTTLE_LDO_SENSE: C2000_Control_Card (J3.20), Input_Signal_Conditioning (C84.2 R72.2 R73.2)
VDC: C2000_Control_Card (J3.21), Gate_Drive (C32.2 R38.2 R39.2)

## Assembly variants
001: not fitted FID1 FID2 FID3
